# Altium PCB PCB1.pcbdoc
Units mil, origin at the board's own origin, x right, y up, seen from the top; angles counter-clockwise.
Board outline 3937 x 2952.8 mil, 2 copper layers (Top Layer, Bottom Layer), stack 62.2 mil thick; 7 components, 26 nets, 76 pads, 0 vias.
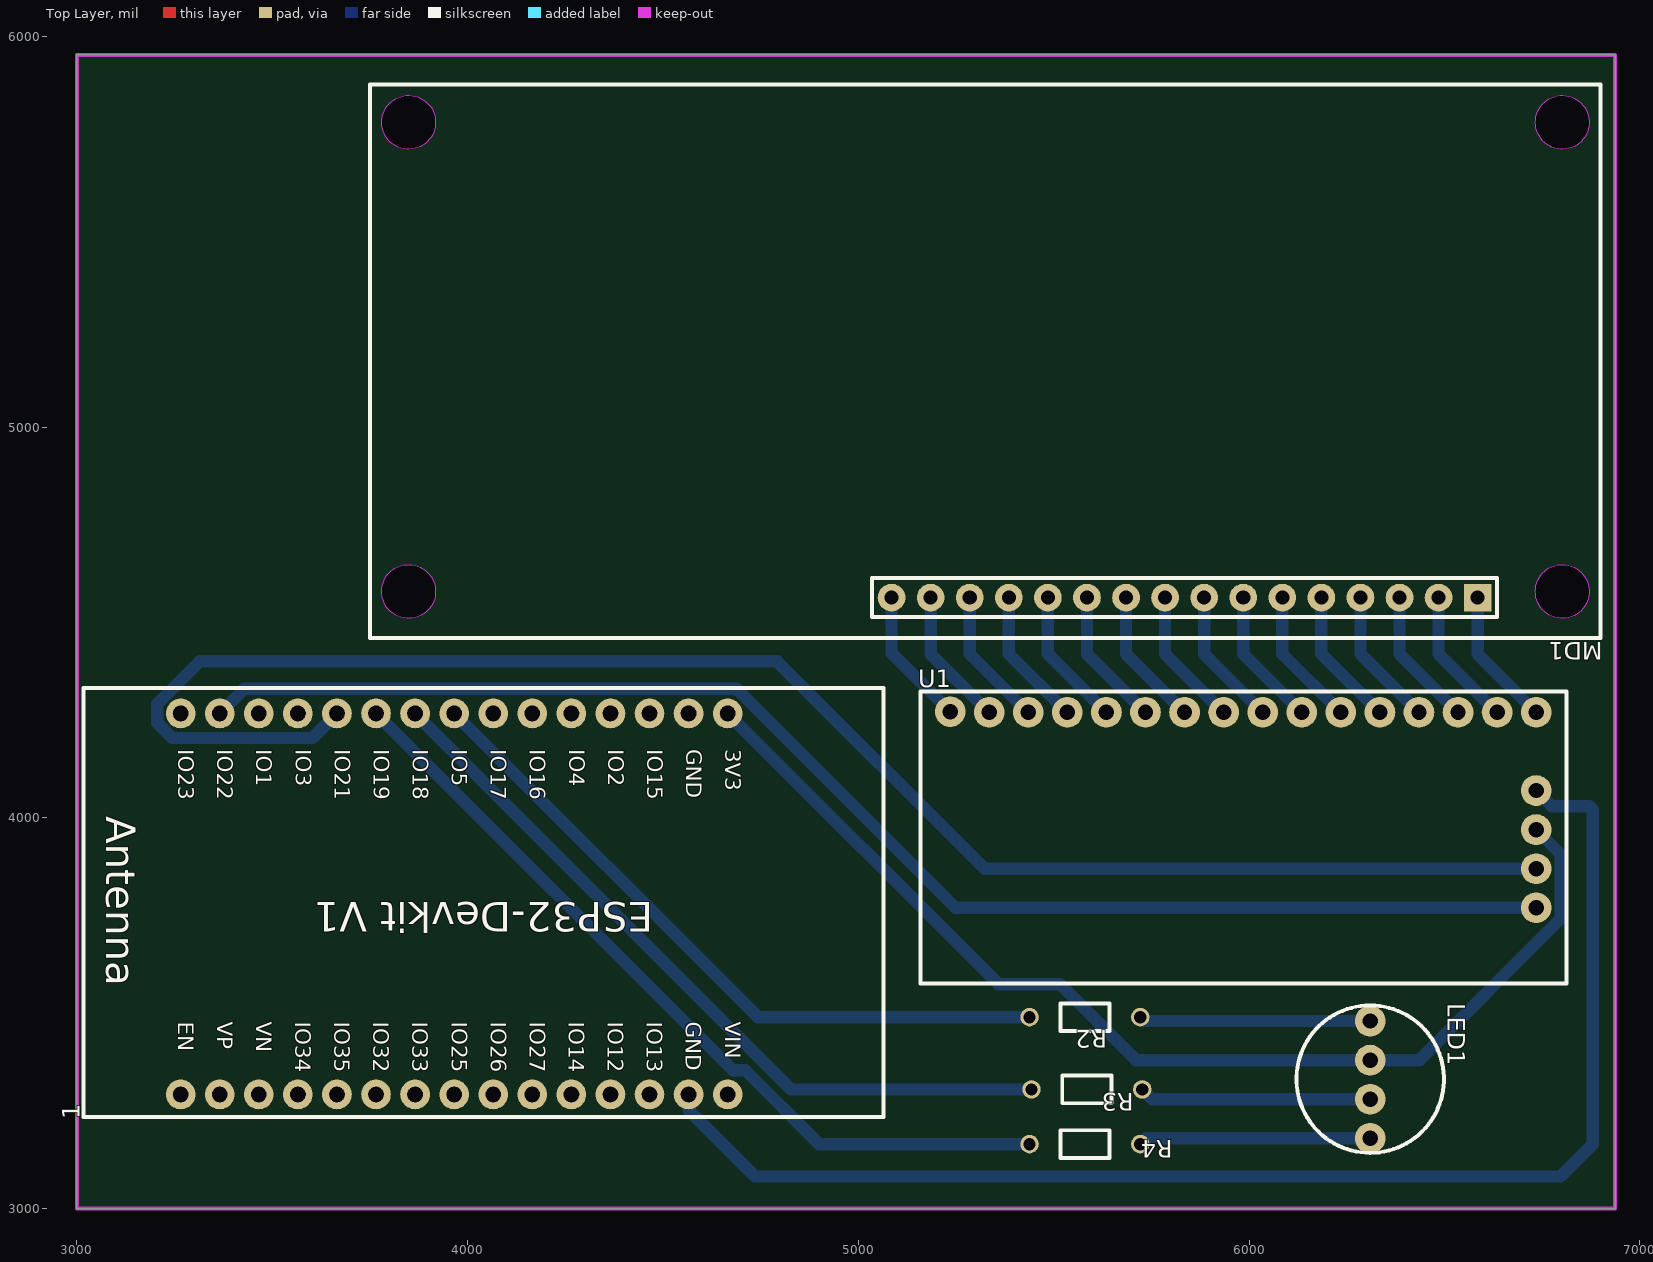
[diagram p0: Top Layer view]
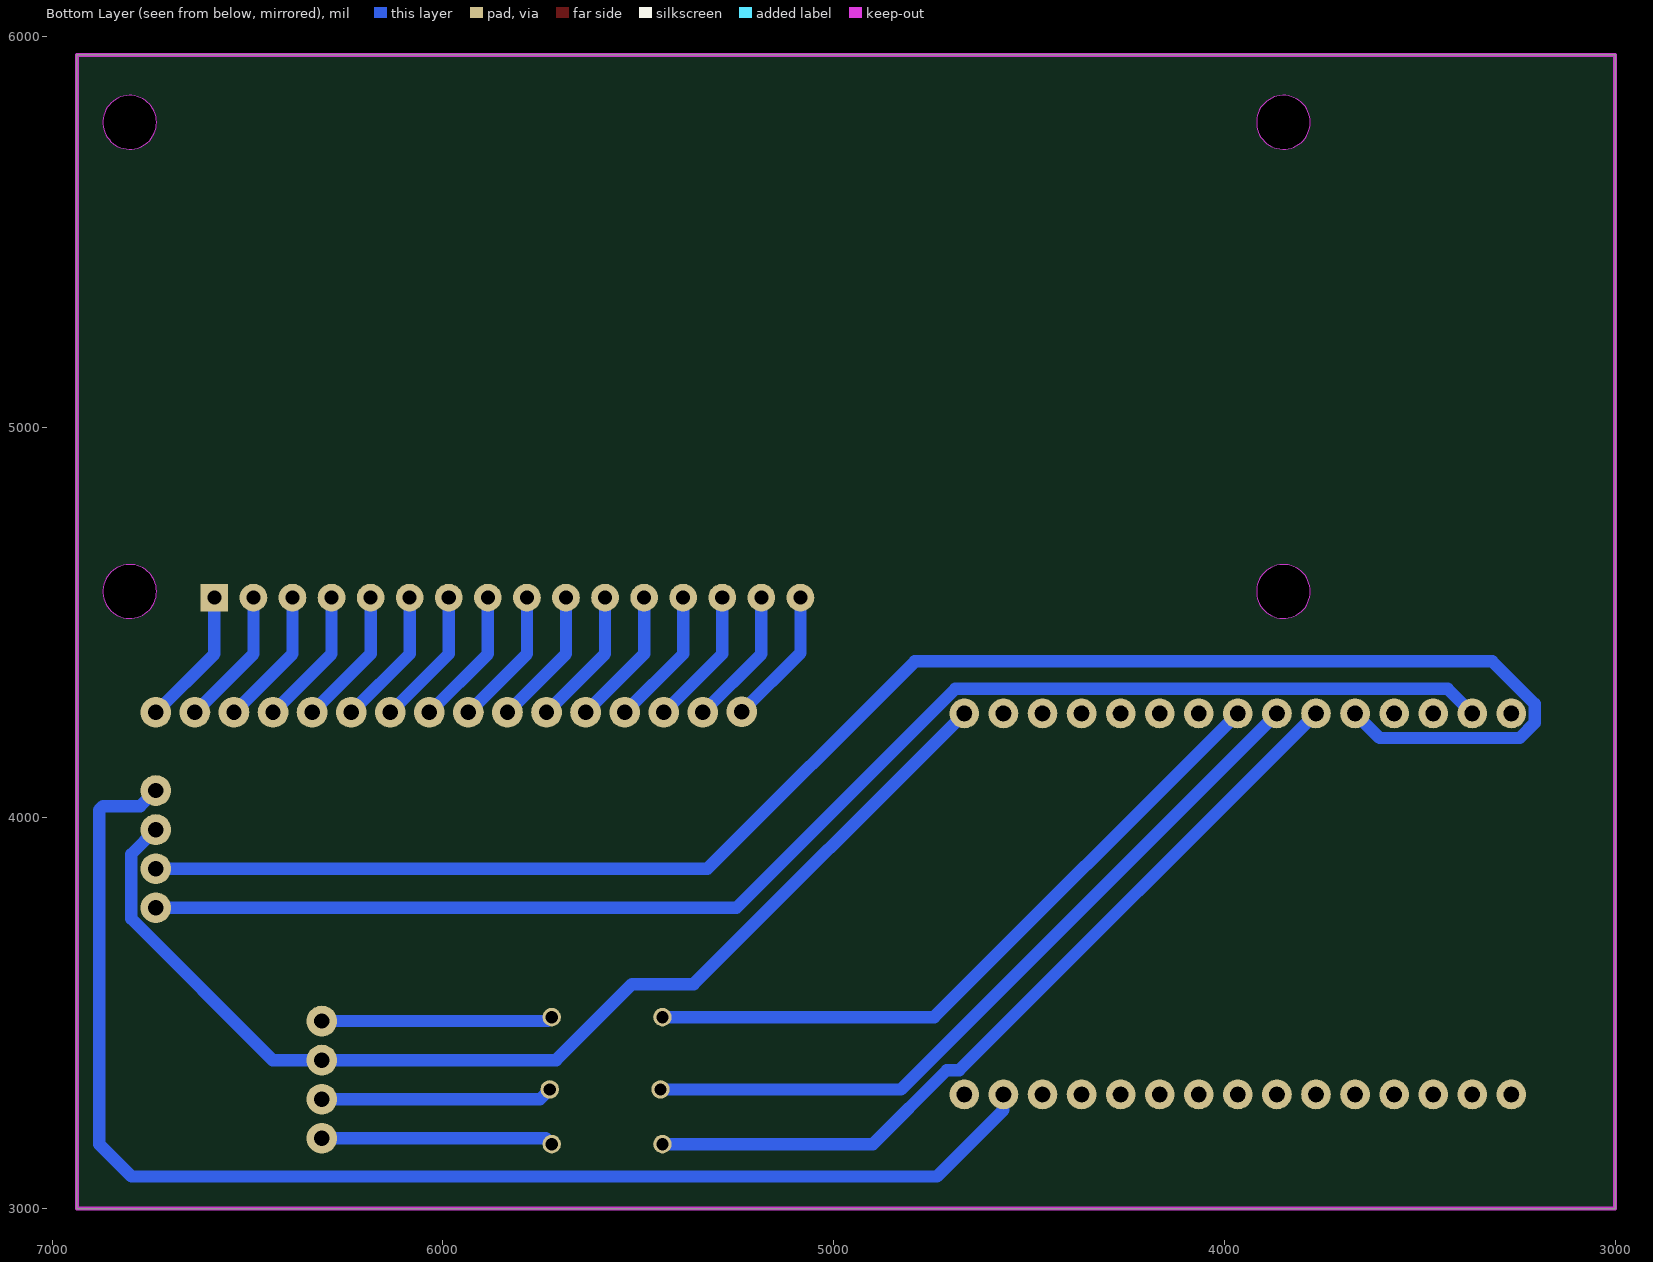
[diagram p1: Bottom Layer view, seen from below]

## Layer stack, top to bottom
Top Solder Mask Layer: solder mask 0.4, Dk 3.3
Top Layer: signal copper 1.4
Dielectric1: surface 59.4, FR4, Dk 4.5
Bottom Layer: signal copper 1.4
Bottom Solder Mask Layer: solder mask 0.4, Dk 3.3

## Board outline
3000,5952.8 3000,3000 6937,3000 6937,5952.8

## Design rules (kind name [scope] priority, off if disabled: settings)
BoardOutlineClearance copperThickness1oz [All] p0: genericclearance=10 ignorepadtopadclearanceinfootprint=FALSE except(0: Arc-SplitContinuation Track-SplitContinuation SMDPad-SplitContinuation THPad-SplitContinuation Via-SplitContinuation Fill-SplitContinuation Poly-SplitContinuation Region-SplitContinuation Text-SplitContinuation)
BoardOutlineClearance copperThickness2oz [All] p0: genericclearance=10 ignorepadtopadclearanceinfootprint=FALSE except(0: Arc-SplitContinuation Track-SplitContinuation SMDPad-SplitContinuation THPad-SplitContinuation Via-SplitContinuation Fill-SplitContinuation Poly-SplitContinuation Region-SplitContinuation Text-SplitContinuation)
BoardOutlineClearance otherClearance [All] p0: genericclearance=10 ignorepadtopadclearanceinfootprint=FALSE except(0: Arc-SplitContinuation Track-SplitContinuation SMDPad-SplitContinuation THPad-SplitContinuation Via-SplitContinuation Fill-SplitContinuation Poly-SplitContinuation Region-SplitContinuation Text-SplitContinuation)
Clearance copperThickness1oz [All] p1: gap=7 ignorepadtopadclearanceinfootprint=FALSE
Clearance copperThickness2oz [All] p1: gap=7 ignorepadtopadclearanceinfootprint=FALSE
Clearance otherClearance [All] p1: gap=7 ignorepadtopadclearanceinfootprint=FALSE
DiffPairsRouting differentialPair [All] p1: maxuncoupledlength=10 minlimit=6 maxlimit=Infinity mostfreqgap=6 toplayer_minwidth=5 toplayer_prefwidth=10 toplayer_maxwidth=100 bottomlayer_minwidth=5 bottomlayer_prefwidth=10 bottomlayer_maxwidth=100
PasteMaskExpansion pasteMaskExpansion [All] p1: expansion=0
PlaneConnect innerPlane [All] p1: planeconnectstyle=Relief reliefexpansion=20 reliefentries=4 reliefconductorwidth=10 reliefairgap=10
PolygonConnect copperRegion [All] p1: connectstyle=Relief reliefentries=4 reliefconductorwidth=10 polygonreliefangle="90 Angle" airgapwidth=10
RoutingVias viaSize [All] p1: viastyle="Through Hole" holewidth=12.0078 minholewidth=11.811 maxholewidth=248.0314 width=12.0078 minwidth=11.811 maxwidth=248.0314
SolderMaskExpansion solderMaskExpansion [IsVia] p1: useseparateexpansions=TRUE expansion=-1000 expansionbottom=-1000
SolderMaskExpansion solderMaskExpansion [All] p2: useseparateexpansions=TRUE expansion=2 expansionbottom=2
Width copperThickness1oz [All] p1: maxlimit=100 minlimit=5 preferedwidth=10
Width copperThickness2oz [All] p1: maxlimit=100 minlimit=8 preferedwidth=10
Width trackWidth1 [All] p1: maxlimit=100 minlimit=5 preferedwidth=31
Width trackWidth2 [All] p1: maxlimit=31 minlimit=31 preferedwidth=31

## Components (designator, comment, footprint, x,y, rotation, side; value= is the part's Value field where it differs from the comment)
1 "ESP32 (DEVKITV1) (AA0)" ESP32-DEVKITV1_ESP32-DEVKITV1 3940,4060 r90 top
LED1 "led_rgb" "LED RGB 5MM (ARL5RGB)" 6310,3330 r270 top
MD1 "DISPLAY-LCD-16X2" DISPLAY-LCD-16X2 5365,5145 r180 top
R2 "10kΩ" RES-TH_BD1.8-L3.2-P7.20-D0.4 5580,3490 r180 top
R3 "10kΩ" RES-TH_BD1.8-L3.2-P7.20-D0.4 5585,3305 r180 top
R4 "10kΩ" RES-TH_BD1.8-L3.2-P7.20-D0.4 5580,3165 r180 top
U1 "lcd_i2c_pcf8574t" "I2C MODULE" 4790,3930 r0 top

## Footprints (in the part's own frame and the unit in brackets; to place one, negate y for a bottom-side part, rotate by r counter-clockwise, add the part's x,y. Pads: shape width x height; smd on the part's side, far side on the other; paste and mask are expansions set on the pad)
DISPLAY-LCD-16X2 [mil]
  rect 70.9x70.9 hole 36 paste+0 mask+4: 1(-1220.2,581.3)
  round 70.9 hole 36 paste+0 mask+4: 2(-1120.2,581.3) 3(-1020.2,581.3) 4(-920.2,581.3) 5(-820.2,581.3) 6(-720.2,581.3) 7(-620.2,581.3) 8(-520.2,581.3) 9(-420.2,581.3) 10(-320.2,581.3) 11(-220.2,581.3) 12(-120.2,581.3) 13(-20.2,581.3) 14(79.8,581.3) 15(179.8,581.3) 16(279.8,581.3)
  Board Outline Layer lines w0.1: 1584.9,565.5 1584.5,558.2 1583.3,551 1581.4,543.9 1578.7,537.1 1575.3,530.6 1571.3,524.5 1566.6,518.8 1561.4,513.7 1555.6,509.2 1549.4,505.3 1542.8,502.1 1535.9,499.6 1528.7,497.8 1521.5,496.9 1514.1,496.7 1506.8,497.3 1499.6,498.6 1492.6,500.7 1485.9,503.6 1479.4,507.1 1473.4,511.4 1467.9,516.2 1462.9,521.6 1458.6,527.5 1454.8,533.8 1451.8,540.5 1449.5,547.4 1448,554.6 1447.2,561.9 1447.2,569.2 1448,576.5 1449.5,583.7 1451.8,590.6 1454.8,597.3 1458.6,603.6 1462.9,609.5 1467.9,614.9 1473.4,619.7 1479.4,624 1485.9,627.5 1492.6,630.4 1499.6,632.5 1506.8,633.8 1514.1,634.4 1521.5,634.2 1528.7,633.3 1535.9,631.5 1542.8,629 1549.4,625.8 1555.6,621.9 1561.4,617.4 1566.6,612.3 1571.3,606.6 1575.3,600.5 1578.7,594 1581.4,587.2 1583.3,580.1 1584.5,572.9 1584.9,565.5 ; 1584.9,-635.2 1584.5,-642.6 1583.3,-649.8 1581.4,-656.9 1578.7,-663.7 1575.3,-670.2 1571.3,-676.3 1566.6,-682 1561.4,-687.1 1555.6,-691.6 1549.4,-695.5 1542.8,-698.7 1535.9,-701.2 1528.7,-702.9 1521.5,-703.9 1514.1,-704.1 1506.8,-703.5 1499.6,-702.2 1492.6,-700.1 1485.9,-697.2 1479.4,-693.6 1473.4,-689.4 1467.9,-684.6 1462.9,-679.2 1458.6,-673.3 1454.8,-667 1451.8,-660.3 1449.5,-653.4 1448,-646.2 1447.2,-638.9 1447.2,-631.6 1448,-624.3 1449.5,-617.1 1451.8,-610.2 1454.8,-603.5 1458.6,-597.2 1462.9,-591.3 1467.9,-585.9 1473.4,-581 1479.4,-576.8 1485.9,-573.3 1492.6,-570.4 1499.6,-568.3 1506.8,-567 1514.1,-566.4 1521.5,-566.6 1528.7,-567.5 1535.9,-569.3 1542.8,-571.8 1549.4,-575 1555.6,-578.9 1561.4,-583.4 1566.6,-588.5 1571.3,-594.2 1575.3,-600.3 1578.7,-606.8 1581.4,-613.6 1583.3,-620.7 1584.5,-627.9 1584.9,-635.2 ; -1367.9,565.5 -1368.3,558.2 -1369.4,551 -1371.4,543.9 -1374,537.1 -1377.4,530.6 -1381.5,524.5 -1386.1,518.8 -1391.4,513.7 -1397.2,509.2 -1403.4,505.3 -1410,502.1 -1416.9,499.6 -1424,497.8 -1431.3,496.9 -1438.6,496.7 -1445.9,497.3 -1453.1,498.6 -1460.1,500.7 -1466.9,503.6 -1473.3,507.1 -1479.3,511.4 -1484.8,516.2 -1489.8,521.6 -1494.2,527.5 -1497.9,533.8 -1500.9,540.5 -1503.2,547.4 -1504.8,554.6 -1505.6,561.9 -1505.6,569.2 -1504.8,576.5 -1503.2,583.7 -1500.9,590.6 -1497.9,597.3 -1494.2,603.6 -1489.8,609.5 -1484.8,614.9 -1479.3,619.7 -1473.3,624 -1466.9,627.5 -1460.1,630.4 -1453.1,632.5 -1445.9,633.8 -1438.6,634.4 -1431.3,634.2 -1424,633.3 -1416.9,631.5 -1410,629 -1403.4,625.8 -1397.2,621.9 -1391.4,617.4 -1386.1,612.3 -1381.5,606.6 -1377.4,600.5 -1374,594 -1371.4,587.2 -1369.4,580.1 -1368.3,572.9 -1367.9,565.5 ; -1367.9,-635.2 -1368.3,-642.6 -1369.4,-649.8 -1371.4,-656.9 -1374,-663.7 -1377.4,-670.2 -1381.5,-676.3 -1386.1,-682 -1391.4,-687.1 -1397.2,-691.6 -1403.4,-695.5 -1410,-698.7 -1416.9,-701.2 -1424,-702.9 -1431.3,-703.9 -1438.6,-704.1 -1445.9,-703.5 -1453.1,-702.2 -1460.1,-700.1 -1466.9,-697.2 -1473.3,-693.6 -1479.3,-689.4 -1484.8,-684.6 -1489.8,-679.2 -1494.2,-673.3 -1497.9,-667 -1500.9,-660.3 -1503.2,-653.4 -1504.8,-646.2 -1505.6,-638.9 -1505.6,-631.6 -1504.8,-624.3 -1503.2,-617.1 -1500.9,-610.2 -1497.9,-603.5 -1494.2,-597.2 -1489.8,-591.3 -1484.8,-585.9 -1479.3,-581 -1473.3,-576.8 -1466.9,-573.3 -1460.1,-570.4 -1453.1,-568.3 -1445.9,-567 -1438.6,-566.4 -1431.3,-566.6 -1424,-567.5 -1416.9,-569.3 -1410,-571.8 -1403.4,-575 -1397.2,-578.9 -1391.4,-583.4 -1386.1,-588.5 -1381.5,-594.2 -1377.4,-600.3 -1374,-606.8 -1371.4,-613.6 -1369.4,-620.7 -1368.3,-627.9 -1367.9,-635.2
  Board Outline Layer region: -1367.9,565.5 -1368.3,558.2 -1369.4,551 -1371.4,543.9 -1374,537.1 -1377.4,530.6 -1381.5,524.5 -1386.1,518.8 -1391.4,513.7 -1397.2,509.2 -1403.4,505.3 -1410,502.1 -1416.9,499.6 -1424,497.8 -1431.3,496.9 -1438.6,496.7 -1445.9,497.3 -1453.1,498.6 -1460.1,500.7 -1466.9,503.6 -1473.3,507.1 -1479.3,511.4 -1484.8,516.2 -1489.8,521.6 -1494.2,527.5 -1497.9,533.8 -1500.9,540.5 -1503.2,547.4 -1504.8,554.6 -1505.6,561.9 -1505.6,569.2 -1504.8,576.5 -1503.2,583.7 -1500.9,590.6 -1497.9,597.3 -1494.2,603.6 -1489.8,609.5 -1484.8,614.9 -1479.3,619.7 -1473.3,624 -1466.9,627.5 -1460.1,630.4 -1453.1,632.5 -1445.9,633.8 -1438.6,634.4 -1431.3,634.2 -1424,633.3 -1416.9,631.5 -1410,629 -1403.4,625.8 -1397.2,621.9 -1391.4,617.4 -1386.1,612.3 -1381.5,606.6 -1377.4,600.5 -1374,594 -1371.4,587.2 -1369.4,580.1 -1368.3,572.9
  Board Outline Layer region: -1367.9,565.5 -1368.3,558.2 -1369.4,551 -1371.4,543.9 -1374,537.1 -1377.4,530.6 -1381.5,524.5 -1386.1,518.8 -1391.4,513.7 -1397.2,509.2 -1403.4,505.3 -1410,502.1 -1416.9,499.6 -1424,497.8 -1431.3,496.9 -1438.6,496.7 -1445.9,497.3 -1453.1,498.6 -1460.1,500.7 -1466.9,503.6 -1473.3,507.1 -1479.3,511.4 -1484.8,516.2 -1489.8,521.6 -1494.2,527.5 -1497.9,533.8 -1500.9,540.5 -1503.2,547.4 -1504.8,554.6 -1505.6,561.9 -1505.6,569.2 -1504.8,576.5 -1503.2,583.7 -1500.9,590.6 -1497.9,597.3 -1494.2,603.6 -1489.8,609.5 -1484.8,614.9 -1479.3,619.7 -1473.3,624 -1466.9,627.5 -1460.1,630.4 -1453.1,632.5 -1445.9,633.8 -1438.6,634.4 -1431.3,634.2 -1424,633.3 -1416.9,631.5 -1410,629 -1403.4,625.8 -1397.2,621.9 -1391.4,617.4 -1386.1,612.3 -1381.5,606.6 -1377.4,600.5 -1374,594 -1371.4,587.2 -1369.4,580.1 -1368.3,572.9
  Board Outline Layer region: -1367.9,-635.2 -1368.3,-642.6 -1369.4,-649.8 -1371.4,-656.9 -1374,-663.7 -1377.4,-670.2 -1381.5,-676.3 -1386.1,-682 -1391.4,-687.1 -1397.2,-691.6 -1403.4,-695.5 -1410,-698.7 -1416.9,-701.2 -1424,-702.9 -1431.3,-703.9 -1438.6,-704.1 -1445.9,-703.5 -1453.1,-702.2 -1460.1,-700.1 -1466.9,-697.2 -1473.3,-693.6 -1479.3,-689.4 -1484.8,-684.6 -1489.8,-679.2 -1494.2,-673.3 -1497.9,-667 -1500.9,-660.3 -1503.2,-653.4 -1504.8,-646.2 -1505.6,-638.9 -1505.6,-631.6 -1504.8,-624.3 -1503.2,-617.1 -1500.9,-610.2 -1497.9,-603.5 -1494.2,-597.2 -1489.8,-591.3 -1484.8,-585.9 -1479.3,-581 -1473.3,-576.8 -1466.9,-573.3 -1460.1,-570.4 -1453.1,-568.3 -1445.9,-567 -1438.6,-566.4 -1431.3,-566.6 -1424,-567.5 -1416.9,-569.3 -1410,-571.8 -1403.4,-575 -1397.2,-578.9 -1391.4,-583.4 -1386.1,-588.5 -1381.5,-594.2 -1377.4,-600.3 -1374,-606.8 -1371.4,-613.6 -1369.4,-620.7 -1368.3,-627.9
  Board Outline Layer region: -1367.9,-635.2 -1368.3,-642.6 -1369.4,-649.8 -1371.4,-656.9 -1374,-663.7 -1377.4,-670.2 -1381.5,-676.3 -1386.1,-682 -1391.4,-687.1 -1397.2,-691.6 -1403.4,-695.5 -1410,-698.7 -1416.9,-701.2 -1424,-702.9 -1431.3,-703.9 -1438.6,-704.1 -1445.9,-703.5 -1453.1,-702.2 -1460.1,-700.1 -1466.9,-697.2 -1473.3,-693.6 -1479.3,-689.4 -1484.8,-684.6 -1489.8,-679.2 -1494.2,-673.3 -1497.9,-667 -1500.9,-660.3 -1503.2,-653.4 -1504.8,-646.2 -1505.6,-638.9 -1505.6,-631.6 -1504.8,-624.3 -1503.2,-617.1 -1500.9,-610.2 -1497.9,-603.5 -1494.2,-597.2 -1489.8,-591.3 -1484.8,-585.9 -1479.3,-581 -1473.3,-576.8 -1466.9,-573.3 -1460.1,-570.4 -1453.1,-568.3 -1445.9,-567 -1438.6,-566.4 -1431.3,-566.6 -1424,-567.5 -1416.9,-569.3 -1410,-571.8 -1403.4,-575 -1397.2,-578.9 -1391.4,-583.4 -1386.1,-588.5 -1381.5,-594.2 -1377.4,-600.3 -1374,-606.8 -1371.4,-613.6 -1369.4,-620.7 -1368.3,-627.9
  Board Outline Layer region: 1584.9,-635.2 1584.5,-642.6 1583.3,-649.8 1581.4,-656.9 1578.7,-663.7 1575.3,-670.2 1571.3,-676.3 1566.6,-682 1561.4,-687.1 1555.6,-691.6 1549.4,-695.5 1542.8,-698.7 1535.9,-701.2 1528.7,-702.9 1521.5,-703.9 1514.1,-704.1 1506.8,-703.5 1499.6,-702.2 1492.6,-700.1 1485.9,-697.2 1479.4,-693.6 1473.4,-689.4 1467.9,-684.6 1462.9,-679.2 1458.6,-673.3 1454.8,-667 1451.8,-660.3 1449.5,-653.4 1448,-646.2 1447.2,-638.9 1447.2,-631.6 1448,-624.3 1449.5,-617.1 1451.8,-610.2 1454.8,-603.5 1458.6,-597.2 1462.9,-591.3 1467.9,-585.9 1473.4,-581 1479.4,-576.8 1485.9,-573.3 1492.6,-570.4 1499.6,-568.3 1506.8,-567 1514.1,-566.4 1521.5,-566.6 1528.7,-567.5 1535.9,-569.3 1542.8,-571.8 1549.4,-575 1555.6,-578.9 1561.4,-583.4 1566.6,-588.5 1571.3,-594.2 1575.3,-600.3 1578.7,-606.8 1581.4,-613.6 1583.3,-620.7 1584.5,-627.9
  Board Outline Layer region: 1584.9,-635.2 1584.5,-642.6 1583.3,-649.8 1581.4,-656.9 1578.7,-663.7 1575.3,-670.2 1571.3,-676.3 1566.6,-682 1561.4,-687.1 1555.6,-691.6 1549.4,-695.5 1542.8,-698.7 1535.9,-701.2 1528.7,-702.9 1521.5,-703.9 1514.1,-704.1 1506.8,-703.5 1499.6,-702.2 1492.6,-700.1 1485.9,-697.2 1479.4,-693.6 1473.4,-689.4 1467.9,-684.6 1462.9,-679.2 1458.6,-673.3 1454.8,-667 1451.8,-660.3 1449.5,-653.4 1448,-646.2 1447.2,-638.9 1447.2,-631.6 1448,-624.3 1449.5,-617.1 1451.8,-610.2 1454.8,-603.5 1458.6,-597.2 1462.9,-591.3 1467.9,-585.9 1473.4,-581 1479.4,-576.8 1485.9,-573.3 1492.6,-570.4 1499.6,-568.3 1506.8,-567 1514.1,-566.4 1521.5,-566.6 1528.7,-567.5 1535.9,-569.3 1542.8,-571.8 1549.4,-575 1555.6,-578.9 1561.4,-583.4 1566.6,-588.5 1571.3,-594.2 1575.3,-600.3 1578.7,-606.8 1581.4,-613.6 1583.3,-620.7 1584.5,-627.9
  Board Outline Layer region: 1584.9,565.5 1584.5,558.2 1583.3,551 1581.4,543.9 1578.7,537.1 1575.3,530.6 1571.3,524.5 1566.6,518.8 1561.4,513.7 1555.6,509.2 1549.4,505.3 1542.8,502.1 1535.9,499.6 1528.7,497.8 1521.5,496.9 1514.1,496.7 1506.8,497.3 1499.6,498.6 1492.6,500.7 1485.9,503.6 1479.4,507.1 1473.4,511.4 1467.9,516.2 1462.9,521.6 1458.6,527.5 1454.8,533.8 1451.8,540.5 1449.5,547.4 1448,554.6 1447.2,561.9 1447.2,569.2 1448,576.5 1449.5,583.7 1451.8,590.6 1454.8,597.3 1458.6,603.6 1462.9,609.5 1467.9,614.9 1473.4,619.7 1479.4,624 1485.9,627.5 1492.6,630.4 1499.6,632.5 1506.8,633.8 1514.1,634.4 1521.5,634.2 1528.7,633.3 1535.9,631.5 1542.8,629 1549.4,625.8 1555.6,621.9 1561.4,617.4 1566.6,612.3 1571.3,606.6 1575.3,600.5 1578.7,594 1581.4,587.2 1583.3,580.1 1584.5,572.9
  Board Outline Layer region: 1584.9,565.5 1584.5,558.2 1583.3,551 1581.4,543.9 1578.7,537.1 1575.3,530.6 1571.3,524.5 1566.6,518.8 1561.4,513.7 1555.6,509.2 1549.4,505.3 1542.8,502.1 1535.9,499.6 1528.7,497.8 1521.5,496.9 1514.1,496.7 1506.8,497.3 1499.6,498.6 1492.6,500.7 1485.9,503.6 1479.4,507.1 1473.4,511.4 1467.9,516.2 1462.9,521.6 1458.6,527.5 1454.8,533.8 1451.8,540.5 1449.5,547.4 1448,554.6 1447.2,561.9 1447.2,569.2 1448,576.5 1449.5,583.7 1451.8,590.6 1454.8,597.3 1458.6,603.6 1462.9,609.5 1467.9,614.9 1473.4,619.7 1479.4,624 1485.9,627.5 1492.6,630.4 1499.6,632.5 1506.8,633.8 1514.1,634.4 1521.5,634.2 1528.7,633.3 1535.9,631.5 1542.8,629 1549.4,625.8 1555.6,621.9 1561.4,617.4 1566.6,612.3 1571.3,606.6 1575.3,600.5 1578.7,594 1581.4,587.2 1583.3,580.1 1584.5,572.9
  Multi-Layer board cut-out: -1367.9,565.5 -1368.3,558.2 -1369.4,551 -1371.4,543.9 -1374,537.1 -1377.4,530.6 -1381.5,524.5 -1386.1,518.8 -1391.4,513.7 -1397.2,509.2 -1403.4,505.3 -1410,502.1 -1416.9,499.6 -1424,497.8 -1431.3,496.9 -1438.6,496.7 -1445.9,497.3 -1453.1,498.6 -1460.1,500.7 -1466.9,503.6 -1473.3,507.1 -1479.3,511.4 -1484.8,516.2 -1489.8,521.6 -1494.2,527.5 -1497.9,533.8 -1500.9,540.5 -1503.2,547.4 -1504.8,554.6 -1505.6,561.9 -1505.6,569.2 -1504.8,576.5 -1503.2,583.7 -1500.9,590.6 -1497.9,597.3 -1494.2,603.6 -1489.8,609.5 -1484.8,614.9 -1479.3,619.7 -1473.3,624 -1466.9,627.5 -1460.1,630.4 -1453.1,632.5 -1445.9,633.8 -1438.6,634.4 -1431.3,634.2 -1424,633.3 -1416.9,631.5 -1410,629 -1403.4,625.8 -1397.2,621.9 -1391.4,617.4 -1386.1,612.3 -1381.5,606.6 -1377.4,600.5 -1374,594 -1371.4,587.2 -1369.4,580.1 -1368.3,572.9
  Multi-Layer board cut-out: -1367.9,-635.2 -1368.3,-642.6 -1369.4,-649.8 -1371.4,-656.9 -1374,-663.7 -1377.4,-670.2 -1381.5,-676.3 -1386.1,-682 -1391.4,-687.1 -1397.2,-691.6 -1403.4,-695.5 -1410,-698.7 -1416.9,-701.2 -1424,-702.9 -1431.3,-703.9 -1438.6,-704.1 -1445.9,-703.5 -1453.1,-702.2 -1460.1,-700.1 -1466.9,-697.2 -1473.3,-693.6 -1479.3,-689.4 -1484.8,-684.6 -1489.8,-679.2 -1494.2,-673.3 -1497.9,-667 -1500.9,-660.3 -1503.2,-653.4 -1504.8,-646.2 -1505.6,-638.9 -1505.6,-631.6 -1504.8,-624.3 -1503.2,-617.1 -1500.9,-610.2 -1497.9,-603.5 -1494.2,-597.2 -1489.8,-591.3 -1484.8,-585.9 -1479.3,-581 -1473.3,-576.8 -1466.9,-573.3 -1460.1,-570.4 -1453.1,-568.3 -1445.9,-567 -1438.6,-566.4 -1431.3,-566.6 -1424,-567.5 -1416.9,-569.3 -1410,-571.8 -1403.4,-575 -1397.2,-578.9 -1391.4,-583.4 -1386.1,-588.5 -1381.5,-594.2 -1377.4,-600.3 -1374,-606.8 -1371.4,-613.6 -1369.4,-620.7 -1368.3,-627.9
  Multi-Layer board cut-out: 1584.9,-635.2 1584.5,-642.6 1583.3,-649.8 1581.4,-656.9 1578.7,-663.7 1575.3,-670.2 1571.3,-676.3 1566.6,-682 1561.4,-687.1 1555.6,-691.6 1549.4,-695.5 1542.8,-698.7 1535.9,-701.2 1528.7,-702.9 1521.5,-703.9 1514.1,-704.1 1506.8,-703.5 1499.6,-702.2 1492.6,-700.1 1485.9,-697.2 1479.4,-693.6 1473.4,-689.4 1467.9,-684.6 1462.9,-679.2 1458.6,-673.3 1454.8,-667 1451.8,-660.3 1449.5,-653.4 1448,-646.2 1447.2,-638.9 1447.2,-631.6 1448,-624.3 1449.5,-617.1 1451.8,-610.2 1454.8,-603.5 1458.6,-597.2 1462.9,-591.3 1467.9,-585.9 1473.4,-581 1479.4,-576.8 1485.9,-573.3 1492.6,-570.4 1499.6,-568.3 1506.8,-567 1514.1,-566.4 1521.5,-566.6 1528.7,-567.5 1535.9,-569.3 1542.8,-571.8 1549.4,-575 1555.6,-578.9 1561.4,-583.4 1566.6,-588.5 1571.3,-594.2 1575.3,-600.3 1578.7,-606.8 1581.4,-613.6 1583.3,-620.7 1584.5,-627.9
  Multi-Layer board cut-out: 1584.9,565.5 1584.5,558.2 1583.3,551 1581.4,543.9 1578.7,537.1 1575.3,530.6 1571.3,524.5 1566.6,518.8 1561.4,513.7 1555.6,509.2 1549.4,505.3 1542.8,502.1 1535.9,499.6 1528.7,497.8 1521.5,496.9 1514.1,496.7 1506.8,497.3 1499.6,498.6 1492.6,500.7 1485.9,503.6 1479.4,507.1 1473.4,511.4 1467.9,516.2 1462.9,521.6 1458.6,527.5 1454.8,533.8 1451.8,540.5 1449.5,547.4 1448,554.6 1447.2,561.9 1447.2,569.2 1448,576.5 1449.5,583.7 1451.8,590.6 1454.8,597.3 1458.6,603.6 1462.9,609.5 1467.9,614.9 1473.4,619.7 1479.4,624 1485.9,627.5 1492.6,630.4 1499.6,632.5 1506.8,633.8 1514.1,634.4 1521.5,634.2 1528.7,633.3 1535.9,631.5 1542.8,629 1549.4,625.8 1555.6,621.9 1561.4,617.4 1566.6,612.3 1571.3,606.6 1575.3,600.5 1578.7,594 1581.4,587.2 1583.3,580.1 1584.5,572.9
  silkscreen extent -1535,-732 1615,685
ESP32-DEVKITV1_ESP32-DEVKITV1 [mil]
  round 76 hole 39.4 paste+0 mask+2: 3V3(207.3,-725.6) D2(207.3,-425.6) D4(207.3,-325.6) D5(207.3,-25.6) D12(-767.9,-425.6) D13(-767.9,-525.6) D14(-767.9,-325.6) D15(207.3,-525.6) D18(207.3,74.4) D19(207.3,174.4) D21(207.3,274.4) D22(207.3,574.4) D23(207.3,674.4) D25(-767.9,-25.6) D26(-767.9,-125.6) D27(-767.9,-225.6) D32(-767.9,174.4) D33(-767.9,74.4) D34(-767.9,374.4) D35(-767.9,274.4) EN(-767.9,674.4) GND(207.3,-625.6) GND2(-767.9,-625.6) RX0(207.3,374.4) RX2(207.3,-225.6) TX0(207.3,474.4) TX2(207.3,-125.6) VIN(-767.9,-725.6) VN(-767.9,474.4) VP(-767.9,574.4)
  silkscreen extent -826,-1124 273,923
"I2C MODULE" [mil]
  round 78.7 hole 39.4 paste+0 mask+4: A(545,340) D0(1345,340) D1(1245,340) D2(1145,340) D3(1045,340) D4(945,340) D5(845,340) D6(745,340) D7(645,340) E(1445,340) GND(1945,140) K(445.4,341.8) RS(1645,340) RW(1545,340) SCL(1945,-160) SDA(1945,-60) V0(1745,340) VCC(1945,40) VDD(1845,340) VSS(1945,340)
  silkscreen extent 369,-354 2022,394
"LED RGB 5MM (ARL5RGB)" [mil]
  round 78.7 hole 39.4 paste+0 mask+4: 1(-50,0) B(150,0) G(50,0) R(-150,0)
  silkscreen extent -190,-189 188,189
RES-TH_BD1.8-L3.2-P7.20-D0.4 [mil]
  round 47.2 hole 31.5: 1(-141.7,0) 2(141.7,0)
  silkscreen extent -63,-35 63,35

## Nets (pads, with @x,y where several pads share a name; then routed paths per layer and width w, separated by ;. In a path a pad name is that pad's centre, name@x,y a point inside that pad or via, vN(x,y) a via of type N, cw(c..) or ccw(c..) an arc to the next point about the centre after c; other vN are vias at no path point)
$1N1009: LED1.B R4.1 | length 594.5
  Bottom Layer w31.5: R4.1 5736.7,3180 LED1.B
$1N1013: 1.D18 R3.2 | length 1976.3
  Bottom Layer w31.5: 1.D18 4827.9,3305 R3.2
$1N1018: MD1.1 U1.VSS | length 355.7
  Bottom Layer w31.5: MD1.1 6585.2,4419.8 U1.VSS
$1N1019: MD1.2 U1.VDD | length 355.7
  Bottom Layer w31.5: MD1.2 6485.2,4419.8 U1.VDD
$1N1020: MD1.3 U1.V0 | length 355.7
  Bottom Layer w31.5: MD1.3 6385.2,4419.8 U1.V0
$1N1021: MD1.4 U1.RS | length 355.7
  Bottom Layer w31.5: MD1.4 6285.2,4419.8 U1.RS
$1N1022: MD1.5 U1.RW | length 355.7
  Bottom Layer w31.5: MD1.5 6185.2,4419.8 U1.RW
$1N1023: MD1.6 U1.E | length 355.7
  Bottom Layer w31.5: MD1.6 6085.2,4419.8 U1.E
$1N1024: MD1.7 U1.D0 | length 355.7
  Bottom Layer w31.5: MD1.7 5985.2,4419.8 U1.D0
$1N1025: MD1.8 U1.D1 | length 355.7
  Bottom Layer w31.5: MD1.8 5885.2,4419.8 U1.D1
$1N1026: MD1.9 U1.D2 | length 355.7
  Bottom Layer w31.5: MD1.9 5785.2,4419.8 U1.D2
$1N1027: MD1.16 U1.K | length 354.1
  Bottom Layer w31.5: MD1.16 5085.2,4422 U1.K
$1N1028: MD1.15 U1.A | length 355.7
  Bottom Layer w31.5: MD1.15 5185.2,4419.8 U1.A
$1N1029: MD1.14 U1.D7 | length 355.7
  Bottom Layer w31.5: MD1.14 5285.2,4419.8 U1.D7
$1N1030: MD1.13 U1.D6 | length 355.7
  Bottom Layer w31.5: MD1.13 5385.2,4419.8 U1.D6
$1N1031: MD1.12 U1.D5 | length 355.7
  Bottom Layer w31.5: MD1.12 5485.2,4419.8 U1.D5
$1N1032: MD1.11 U1.D4 | length 355.7
  Bottom Layer w31.5: MD1.11 5585.2,4419.8 U1.D4
$1N1033: MD1.10 U1.D3 | length 355.7
  Bottom Layer w31.5: MD1.10 5685.2,4419.8 U1.D3
$1N1042: 1.D21 U1.SDA | length 4345
  Bottom Layer w31.5: 1.D21 3602.6,4204.3 3244.2,4204.3 3205.9,4242.6 3205.9,4292.1 3314.5,4400.6 4792.2,4400.6 5322.8,3870 U1.SDA
$1N1044: 1.D22 U1.SCL | length 3627.6
  Bottom Layer w31.5: 1.D22 3428.6,4330.3 4688.5,4330.3 5248.8,3770 U1.SCL
$1N1050: 1.D5 R2.2 | length 1794.7
  Bottom Layer w31.5: 1.D5 4742.9,3490 R2.2
$1N1056: LED1.G R3.1 | length 593.7
  Bottom Layer w31.5: R3.1 5751.7,3280 LED1.G
$1N1057: LED1.R R2.1 | length 592.4
  Bottom Layer w31.5: R2.1 5731.7,3480 LED1.R
$1N1063: 1.D19 R4.2 | length 2129.3
  Bottom Layer w31.5: 1.D19 4679,3353.9 4710.5,3353.9 4899.4,3165 R4.2
GND: 1.GND2 U1.GND | length 3479.9
  Bottom Layer w31.5: 1.GND2 4565.6,3252.1 4735.6,3082.1 6797.1,3082.1 6880,3165 6880,4020 6870,4030 6775,4030 U1.GND
VCC: 1.3V3 LED1.1 U1.VCC | length 2904
  Bottom Layer w31.5: 1.3V3 5358.5,3574.4 5516,3574.4 5710.4,3380 LED1.1 6436,3380 6798,3742 6798,3907 U1.VCC
pads on no net: 1.D2 1.D4 1.D12 1.D13 1.D14 1.D15 1.D23 1.D25 1.D26 1.D27 1.D32 1.D33 1.D34 1.D35 1.EN 1.GND 1.RX0 1.RX2 1.TX0 1.TX2 1.VIN 1.VN 1.VP

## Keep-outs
Board Outline Layer:
  the board outline again, w10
